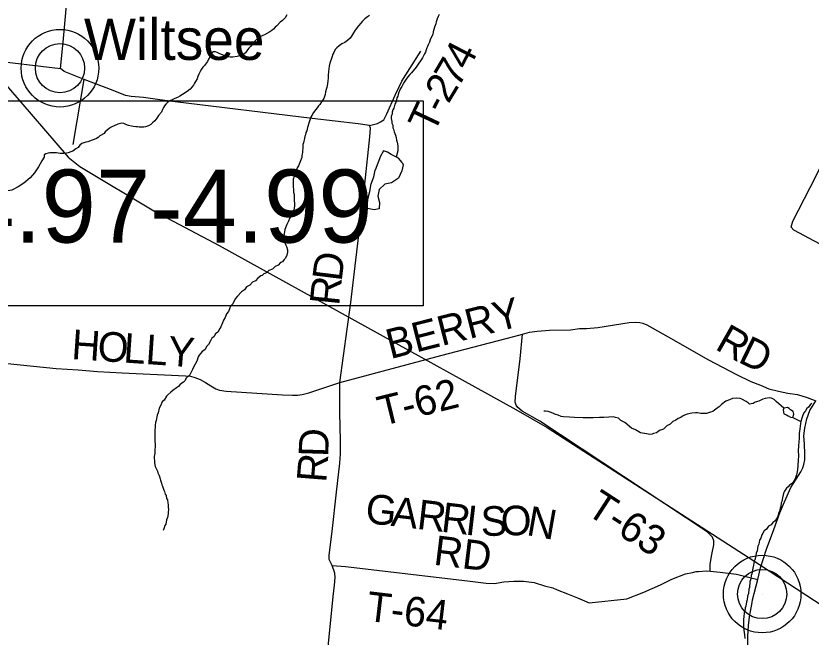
# Model space of a CAD drawing. Extents: x 0 to 39.3, y -3.9 to 22.
# Drawn here: x 6.099 to 7.624, y 15.488 to 16.679 of the extents above; entities that cross this region are included whole.
import ezdxf

# ---------------------------------------------------------------- set-up
doc = ezdxf.new("R2010")
doc.units = 0
for name, color, linetype in [('GM_X_County_Road', 7, 'Continuous'), ('GM_X_County_Road_Text', 7, 'Continuous'), ('GM_X_Minor_Lake', 7, 'Continuous'), ('GM_X_Minor_River', 7, 'Continuous'), ('GM_X_Rail_Line', 7, 'Continuous'), ('GM_X_State_Route', 7, 'Continuous'), ('GM_X_Township_Road', 7, 'Continuous'), ('GM_X_Township_Road_Text', 7, 'Continuous'), ('GM_X_Unincorporated', 7, 'Continuous'), ('GM_X_Unincorporated_Location', 7, 'Continuous'), ('GM_X_Unincorporated_Text', 7, 'Continuous'), ('SH_Text', 7, 'Continuous')]:
    doc.layers.add(name, color=color, linetype=linetype)

msp = doc.modelspace()

# ---------------------------------------------------------------- linework, layer by layer
at = {"layer": 'GM_X_County_Road'}
for points in [[(6.7775, 16.4687), (6.7555, 16.4724), (6.6671, 16.4823), (6.4045, 16.5144), (6.3754, 16.5183), (6.3437, 16.5225), (6.3203, 16.5247), (6.3095, 16.5263), (6.2855, 16.5361), (6.2304, 16.5573), (6.1919, 16.5725), (6.1845, 16.5782), (6.1899, 16.6288), (6.2, 16.7428), (6.219, 16.9267), (6.2251, 16.9948), (6.2341, 17.078), (6.2503, 17.2345), (6.2622, 17.3562), (6.267, 17.3776)], [(6.7203, 15.976), (6.7413, 16.1292), (6.7681, 16.3564), (6.7779, 16.4474), (6.7791, 16.4635), (6.7775, 16.4687)], [(6.0268, 16.0202), (6.0514, 16.0165), (6.0628, 16.015), (6.083, 16.0122), (6.1762, 16.0027), (6.2187, 16.0002), (6.2558, 15.9974), (6.3028, 15.9945), (6.4246, 15.9891), (6.4343, 15.9879), (6.4423, 15.9854), (6.4525, 15.9817), (6.4631, 15.976), (6.4731, 15.9697), (6.4828, 15.9637), (6.4896, 15.9614), (6.5024, 15.9597), (6.6105, 15.9526), (6.6296, 15.9515), (6.6393, 15.9517), (6.6484, 15.9529), (6.661, 15.956), (6.7203, 15.976)]]:
    msp.add_lwpolyline(points, dxfattribs=at)
at = {"layer": 'GM_X_Minor_Lake'}
for points in [[(6.8402, 16.398), (6.8328, 16.4061), (6.8188, 16.4136), (6.8117, 16.4179), (6.8041, 16.4203), (6.7986, 16.4101), (6.7883, 16.3835)], [(6.8402, 16.398), (6.842, 16.3932), (6.8395, 16.3818), (6.8332, 16.3682), (6.8198, 16.359), (6.8068, 16.3562), (6.796, 16.3461), (6.7935, 16.3336), (6.7967, 16.321), (6.7957, 16.3092), (6.7862, 16.3075), (6.7734, 16.3096), (6.7735, 16.3199), (6.7748, 16.3301), (6.7777, 16.3426), (6.7806, 16.357), (6.7854, 16.3702), (6.7883, 16.3835)], [(7.5895, 15.909), (7.5911, 15.915), (7.59, 15.9204), (7.5848, 15.9239), (7.5822, 15.9262), (7.5788, 15.9282), (7.5719, 15.9268), (7.5707, 15.9234), (7.5721, 15.9157)], [(7.5721, 15.9157), (7.5774, 15.9141), (7.5804, 15.9118), (7.5845, 15.9094), (7.5895, 15.909)], [(7.5895, 15.909), (7.6047, 15.901)]]:
    msp.add_lwpolyline(points, dxfattribs=at)
at = {"layer": 'GM_X_Minor_River'}
for points in [[(6.6189, 16.6809), (6.6158, 16.6757), (6.6103, 16.6704), (6.6061, 16.6671), (6.5999, 16.6603), (6.5964, 16.6574), (6.593, 16.654), (6.5899, 16.6514), (6.586, 16.6484), (6.5757, 16.6429), (6.5726, 16.6418), (6.5657, 16.6385), (6.5619, 16.6351), (6.5564, 16.6291), (6.5529, 16.625), (6.5494, 16.6205), (6.546, 16.6172), (6.5436, 16.6142), (6.5394, 16.6085), (6.5363, 16.6055), (6.5313, 16.6033), (6.5236, 16.6012), (6.5149, 16.5998), (6.5103, 16.5999), (6.5065, 16.6007), (6.502, 16.602), (6.4937, 16.6051), (6.4891, 16.6071), (6.485, 16.6087), (6.482, 16.6099), (6.4782, 16.6104), (6.4751, 16.6081), (6.4731, 16.6047), (6.4708, 16.5998), (6.4688, 16.5961), (6.4665, 16.5919), (6.4645, 16.5889), (6.4606, 16.584), (6.4579, 16.5807), (6.4552, 16.5769), (6.4524, 16.5724), (6.4501, 16.5675), (6.4481, 16.5626), (6.4465, 16.5584), (6.4438, 16.5535), (6.4418, 16.5501), (6.4398, 16.5464), (6.4336, 16.5389), (6.4278, 16.534), (6.4186, 16.5281), (6.4133, 16.5255), (6.409, 16.5229), (6.4041, 16.5207), (6.3987, 16.5182), (6.3945, 16.516), (6.3899, 16.513), (6.3868, 16.51), (6.3844, 16.5066), (6.3825, 16.5032), (6.3805, 16.4995), (6.3781, 16.4942), (6.3727, 16.4878), (6.3692, 16.4833), (6.3657, 16.4781), (6.3611, 16.474), (6.358, 16.471), (6.3534, 16.4684), (6.348, 16.4662), (6.3446, 16.4659), (6.3412, 16.4659), (6.3355, 16.4657), (6.3324, 16.4661), (6.3294, 16.4661), (6.3241, 16.467), (6.321, 16.4674), (6.315, 16.4691), (6.3101, 16.471), (6.3063, 16.4726), (6.3025, 16.4735)], [(6.7774, 16.68), (6.7732, 16.6771), (6.7686, 16.6734), (6.7631, 16.6681), (6.7608, 16.6651), (6.7562, 16.6599), (6.7499, 16.6516), (6.7464, 16.6467), (6.7445, 16.6433), (6.7425, 16.6403), (6.7402, 16.6366), (6.7352, 16.6317), (6.7298, 16.6284), (6.7244, 16.6254), (6.7194, 16.6217), (6.7148, 16.618), (6.7117, 16.6146), (6.7089, 16.609), (6.7073, 16.6056), (6.705, 16.5995), (6.7038, 16.5957), (6.7025, 16.592), (6.7013, 16.5882), (6.7001, 16.5829), (6.6993, 16.5779), (6.6988, 16.5722), (6.6983, 16.565), (6.6978, 16.5601), (6.6977, 16.554), (6.6969, 16.5495), (6.6961, 16.5453), (6.6956, 16.5415), (6.6944, 16.5381), (6.6932, 16.5332), (6.6924, 16.5282), (6.6912, 16.5248), (6.69, 16.521), (6.6853, 16.5143), (6.6818, 16.5094), (6.6798, 16.5064), (6.6771, 16.5026), (6.6744, 16.4996), (6.6701, 16.494), (6.667, 16.4884), (6.6646, 16.4846), (6.6614, 16.4755), (6.6586, 16.4649), (6.657, 16.4589), (6.6554, 16.4555), (6.6546, 16.4513), (6.6534, 16.4483), (6.6525, 16.4437), (6.6513, 16.4388), (6.6505, 16.4358), (6.6497, 16.4324), (6.6492, 16.4286), (6.6492, 16.4251), (6.6487, 16.4213), (6.6487, 16.4179), (6.6482, 16.4141), (6.6478, 16.4111), (6.6474, 16.4077)], [(6.9109, 16.6815), (6.9093, 16.6777), (6.9073, 16.6732), (6.9049, 16.6675), (6.9045, 16.6637), (6.9017, 16.6577), (6.9009, 16.6532), (6.8997, 16.6486), (6.8985, 16.6437), (6.8961, 16.6388), (6.8937, 16.6331), (6.8921, 16.6286), (6.8901, 16.6237), (6.8889, 16.6206), (6.8874, 16.6176), (6.8862, 16.6142), (6.8846, 16.6097), (6.883, 16.6063), (6.8791, 16.5988), (6.8752, 16.5927), (6.872, 16.5882), (6.8666, 16.5807), (6.8643, 16.5777), (6.8604, 16.5732), (6.8577, 16.5702), (6.855, 16.5665), (6.8511, 16.562), (6.8476, 16.5578), (6.8437, 16.5518), (6.8413, 16.5477), (6.8394, 16.5439), (6.837, 16.5398), (6.835, 16.5356), (6.8339, 16.5326), (6.8326, 16.5284), (6.8315, 16.5254), (6.8299, 16.522), (6.829, 16.5175), (6.8278, 16.5133), (6.8262, 16.5099), (6.8238, 16.5023), (6.8223, 16.4989), (6.821, 16.4944), (6.8206, 16.4914), (6.819, 16.4864), (6.8189, 16.4823), (6.82, 16.4769), (6.8203, 16.4731), (6.8218, 16.4693), (6.8224, 16.4647), (6.8235, 16.4616), (6.8246, 16.4571), (6.8261, 16.4536), (6.8271, 16.4505), (6.8286, 16.446), (6.8293, 16.441), (6.8303, 16.4368), (6.831, 16.4337), (6.8317, 16.4292), (6.832, 16.4246), (6.832, 16.4204), (6.8286, 16.4084)], [(6.3025, 16.4735), (6.2949, 16.4717), (6.2818, 16.4655), (6.278, 16.4629), (6.2745, 16.4599), (6.2703, 16.4565), (6.2687, 16.4535), (6.2603, 16.4491), (6.2568, 16.4457), (6.2537, 16.4443), (6.2491, 16.4424), (6.2457, 16.4406), (6.2373, 16.4373), (6.2335, 16.437), (6.2293, 16.4359), (6.2254, 16.4345), (6.222, 16.4311), (6.2188, 16.4266), (6.2142, 16.424), (6.2081, 16.4196), (6.2046, 16.4185), (6.1997, 16.4163), (6.1959, 16.416), (6.1909, 16.4153), (6.1871, 16.415), (6.1841, 16.4154), (6.1799, 16.4159), (6.1769, 16.4163), (6.1734, 16.4168), (6.1696, 16.4165), (6.1643, 16.4162), (6.1609, 16.4158), (6.1567, 16.4148), (6.1536, 16.4126), (6.1535, 16.4084)], [(6.1535, 16.4084), (6.149, 16.4012), (6.1423, 16.3895), (6.1349, 16.3783), (6.1268, 16.3685), (6.1141, 16.3585), (6.1037, 16.3515), (6.0914, 16.3448), (6.0789, 16.3428), (6.0679, 16.3437), (6.0474, 16.3441), (6.0352, 16.3413), (6.0221, 16.3274), (6.0135, 16.3143), (6.0042, 16.3015), (5.9944, 16.2868), (5.9847, 16.2726), (5.9745, 16.2572), (5.9633, 16.2441), (5.9525, 16.2306), (5.9439, 16.2178), (5.9327, 16.2051)], [(6.6474, 16.4077), (6.6411, 16.3918), (6.6387, 16.388), (6.6375, 16.3831), (6.6335, 16.3748), (6.6331, 16.3714), (6.6311, 16.3661), (6.6309, 16.3535), (6.6315, 16.344), (6.6318, 16.3413), (6.6328, 16.3368), (6.6328, 16.3326), (6.633, 16.3265), (6.6336, 16.3181), (6.6336, 16.315), (6.6331, 16.3105), (6.6315, 16.3033), (6.6291, 16.2999), (6.6271, 16.2938), (6.624, 16.2905), (6.622, 16.2856), (6.6185, 16.2791), (6.6161, 16.2727), (6.6149, 16.2693), (6.6136, 16.261), (6.6127, 16.2549), (6.613, 16.2507), (6.6152, 16.2442), (6.617, 16.2396), (6.6181, 16.2369), (6.6199, 16.2308), (6.6202, 16.2258), (6.6189, 16.2205), (6.6165, 16.2145), (6.6135, 16.2122), (6.6107, 16.2077), (6.6065, 16.2059), (6.6022, 16.201), (6.5965, 16.1988), (6.5914, 16.1932), (6.5845, 16.1907), (6.5799, 16.1862), (6.5749, 16.1844), (6.5714, 16.1814), (6.5687, 16.1803), (6.5633, 16.1762), (6.559, 16.1713), (6.5529, 16.1684), (6.5478, 16.1624), (6.5417, 16.1594), (6.5374, 16.1538), (6.5316, 16.1501), (6.5239, 16.1415), (6.52, 16.1366), (6.5152, 16.1271), (6.5106, 16.1223), (6.507, 16.1124), (6.5031, 16.1079), (6.5003, 16.1004), (6.4975, 16.0959), (6.4955, 16.0906), (6.492, 16.0826), (6.4904, 16.0796), (6.4865, 16.0728), (6.4818, 16.0695), (6.4787, 16.0638), (6.4752, 16.0612), (6.4725, 16.0559), (6.4685, 16.0488), (6.4654, 16.0458), (6.4615, 16.0386), (6.4565, 16.0357), (6.4541, 16.0323), (6.4506, 16.0285), (6.4487, 16.0251), (6.4462, 16.0168), (6.4404, 16.0066), (6.4376, 16.001), (6.4364, 15.9983), (6.4328, 15.9908), (6.4251, 15.9837), (6.4239, 15.9799), (6.4204, 15.9769), (6.4177, 15.9747), (6.4138, 15.9717), (6.4107, 15.9683), (6.4069, 15.9661), (6.3999, 15.9605), (6.3961, 15.9572), (6.3903, 15.9527), (6.3883, 15.9497), (6.3832, 15.9421), (6.3794, 15.9388), (6.3766, 15.9316), (6.3742, 15.9271), (6.3721, 15.9176), (6.3701, 15.9131), (6.3684, 15.9032), (6.3668, 15.8994), (6.366, 15.8945), (6.3657, 15.8808)], [(7.5719, 15.9268), (7.5571, 15.9398), (7.5534, 15.9437), (7.5485, 15.9457), (7.5447, 15.9465), (7.5359, 15.9455), (7.5317, 15.9441), (7.524, 15.9404), (7.5171, 15.9386), (7.5129, 15.936), (7.5091, 15.935), (7.5064, 15.9346), (7.5034, 15.937), (7.4997, 15.9397), (7.4917, 15.944), (7.488, 15.9452), (7.4807, 15.9457), (7.4735, 15.9455), (7.4677, 15.9425), (7.4605, 15.94), (7.4527, 15.9336), (7.4477, 15.9292), (7.4442, 15.9269), (7.4388, 15.9232), (7.4357, 15.9206), (7.4311, 15.9192), (7.4235, 15.9166), (7.417, 15.9164), (7.4128, 15.9168), (7.4064, 15.9177), (7.4029, 15.9177), (7.3957, 15.9171), (7.3865, 15.9154), (7.3816, 15.9135), (7.3777, 15.9117), (7.3742, 15.9091), (7.3693, 15.9073), (7.365, 15.9035), (7.3593, 15.9014), (7.3542, 15.8961), (7.3473, 15.8932), (7.3415, 15.8868), (7.3334, 15.8839), (7.3276, 15.8794), (7.3223, 15.878), (7.3192, 15.8769), (7.3147, 15.8766), (7.3086, 15.8775), (7.2972, 15.8792), (7.2874, 15.8851), (7.2799, 15.8886), (7.2671, 15.8991), (7.2596, 15.9031), (7.2547, 15.9077), (7.2494, 15.909), (7.2445, 15.9102), (7.2365, 15.9096), (7.2269, 15.909), (7.2182, 15.9087), (7.2064, 15.9082), (7.1869, 15.9081), (7.1702, 15.9088), (7.1611, 15.9093), (7.1493, 15.9103), (7.1447, 15.9111), (7.1391, 15.9131), (7.1326, 15.9155), (7.1289, 15.9175), (7.1239, 15.9191), (7.1202, 15.9203), (7.1148, 15.9208), (7.1114, 15.9212)], [(7.6193, 15.9286), (7.6162, 15.926), (7.6138, 15.9214), (7.6103, 15.9181), (7.6087, 15.9135), (7.6063, 15.9075), (7.6047, 15.901), (7.6039, 15.8973), (7.6025, 15.887), (7.6021, 15.8821), (7.6016, 15.8786), (7.6015, 15.8707), (7.6009, 15.8604), (7.6001, 15.8562), (7.5998, 15.8429), (7.6001, 15.8379), (7.6, 15.8326), (7.5996, 15.8288), (7.5995, 15.825), (7.599, 15.8197), (7.5986, 15.817), (7.5985, 15.8083), (7.5972, 15.8018), (7.5964, 15.7992), (7.5952, 15.795), (7.5932, 15.7901), (7.5885, 15.7833), (7.5831, 15.7792), (7.5804, 15.7762), (7.5773, 15.7732), (7.573, 15.7676), (7.5718, 15.765), (7.5709, 15.7608), (7.5693, 15.7551), (7.568, 15.7479), (7.5669, 15.7453), (7.566, 15.738), (7.5652, 15.735), (7.5639, 15.7286), (7.5619, 15.7255), (7.5611, 15.7214), (7.5591, 15.7165), (7.5548, 15.7101), (7.5509, 15.7075), (7.5474, 15.703), (7.5428, 15.7007), (7.5389, 15.6947), (7.5343, 15.6918), (7.5319, 15.6869), (7.5296, 15.6842), (7.5279, 15.6774), (7.5256, 15.6736), (7.5239, 15.6661), (7.5223, 15.6623), (7.5207, 15.6535), (7.5187, 15.6486), (7.5174, 15.6407), (7.5162, 15.6361), (7.5154, 15.6335), (7.5141, 15.6255), (7.5128, 15.6198), (7.5107, 15.6088), (7.5095, 15.6062), (7.509, 15.5993), (7.507, 15.5936), (7.5061, 15.583), (7.5052, 15.58), (7.5043, 15.5712), (7.5023, 15.5663), (7.5014, 15.5591), (7.5006, 15.5557), (7.4993, 15.547), (7.4977, 15.5436), (7.4969, 15.5371), (7.496, 15.5341), (7.4955, 15.5265), (7.4947, 15.5219), (7.4944, 15.5063), (7.4951, 15.5017), (7.4957, 15.496), (7.4968, 15.4926), (7.4974, 15.4853)], [(7.6259, 15.9357), (7.6224, 15.9331), (7.6193, 15.9286)], [(6.3657, 15.8808), (6.3656, 15.8739), (6.3655, 15.8652), (6.3661, 15.8557), (6.3658, 15.8442), (6.3654, 15.8404), (6.3645, 15.834), (6.3645, 15.8309), (6.3647, 15.8256), (6.3651, 15.8218), (6.3665, 15.8149), (6.3676, 15.8122), (6.3705, 15.8057), (6.3716, 15.803), (6.3738, 15.7977), (6.3756, 15.7915), (6.3766, 15.7885), (6.3781, 15.7827), (6.3788, 15.7797), (6.3806, 15.777), (6.3828, 15.7697), (6.3842, 15.767), (6.3857, 15.7621), (6.3875, 15.7594), (6.3882, 15.7536), (6.3897, 15.751), (6.3903, 15.7449), (6.391, 15.7418), (6.3913, 15.7361), (6.3916, 15.733), (6.3915, 15.7269), (6.3911, 15.7243), (6.3898, 15.7171), (6.3882, 15.7125), (6.3865, 15.7046), (6.385, 15.7016), (6.3834, 15.6974), (6.3815, 15.6923)]]:
    msp.add_lwpolyline(points, dxfattribs=at)
at = {"layer": 'GM_X_Rail_Line'}
msp.add_lwpolyline([(5.9697, 16.6744), (6.1991, 16.4081), (6.2218, 16.3901), (6.3667, 16.3031), (6.4893, 16.2389), (7.0583, 15.9241), (7.1182, 15.89), (7.5253, 15.6271), (8.2122, 15.1777), (8.5334, 14.9668), (8.7, 14.8573)], dxfattribs=at)
at = {"layer": 'GM_X_State_Route'}
for points in [[(7.5122, 15.5592), (7.522, 15.5982), (7.5272, 15.6204), (7.5387, 15.6566), (7.5526, 15.6942), (7.5643, 15.7262), (7.5732, 15.747), (7.5854, 15.7747), (7.6044, 15.8045), (7.6082, 15.8123), (7.6103, 15.8185), (7.6123, 15.8277), (7.6125, 15.839), (7.6114, 15.8576), (7.6105, 15.8736), (7.6124, 15.8884), (7.6161, 15.9066), (7.622, 15.9225), (7.6335, 15.9408)], [(7.5062, 14.9738), (7.5079, 14.9918), (7.5101, 15.0116), (7.5109, 15.0289), (7.5099, 15.057), (7.5076, 15.0895), (7.5041, 15.1204), (7.4986, 15.1789), (7.4952, 15.2192), (7.4944, 15.2368), (7.4931, 15.2662), (7.4943, 15.2903), (7.4956, 15.3156), (7.4974, 15.3466), (7.5005, 15.3886), (7.5027, 15.4261), (7.503, 15.4463), (7.5032, 15.4895), (7.5041, 15.5091), (7.506, 15.5264), (7.511, 15.5543), (7.5122, 15.5592)]]:
    msp.add_lwpolyline(points, dxfattribs=at)
at = {"layer": 'GM_X_Township_Road'}
for p, q in [((6.855, 16.5784), (6.876, 16.6113)), ((6.2088, 16.4325), (6.2304, 16.5573))]:
    msp.add_line(p, q, dxfattribs=at)
for points in [[(5.7323, 16.6297), (5.7442, 16.6283), (5.8452, 16.6172), (6.0439, 16.5946), (6.1845, 16.5782)], [(6.7775, 16.4687), (6.7853, 16.4706), (6.7925, 16.4728), (6.7982, 16.4758), (6.8047, 16.4797), (6.8107, 16.4913), (6.8264, 16.5269), (6.8338, 16.5416), (6.8394, 16.5541), (6.855, 16.5784)], [(7.7438, 16.1805), (7.7386, 16.1846), (7.7284, 16.1927), (7.7122, 16.2024), (7.6705, 16.2262), (7.5912, 16.2683), (7.5862, 16.2741), (7.5891, 16.2854), (7.6332, 16.3712), (7.652, 16.409)], [(6.7203, 15.976), (6.9139, 16.0279), (7.0542, 16.0644), (7.071, 16.0689), (7.0844, 16.0723), (7.0989, 16.0746), (7.1223, 16.0766), (7.1631, 16.077), (7.1802, 16.0793), (7.1934, 16.0793), (7.2151, 16.0817), (7.2751, 16.0912), (7.2871, 16.0917), (7.2959, 16.0914), (7.3016, 16.09), (7.3093, 16.0869), (7.3504, 16.0635), (7.4277, 16.0193), (7.4813, 15.9914), (7.5089, 15.9778), (7.5275, 15.971), (7.5435, 15.964), (7.5621, 15.9592), (7.5796, 15.9557), (7.598, 15.9528), (7.6166, 15.9474), (7.6335, 15.9408)], [(7.4308, 15.6139), (7.4305, 15.6276), (7.434, 15.6461), (7.4376, 15.6644), (7.4376, 15.6724), (7.4354, 15.6795), (7.4251, 15.6896), (7.1041, 15.9021), (7.0701, 15.9212), (7.0621, 15.9278), (7.0584, 15.9323), (7.057, 15.9386), (7.0573, 15.9495), (7.0664, 16.0213), (7.071, 16.0689)], [(6.5996, 14.4912), (6.7035, 15.5268), (6.7077, 15.5659), (6.7103, 15.5876), (6.7116, 15.6022), (6.7108, 15.6105), (6.7059, 15.6251), (6.7001, 15.6366), (6.6999, 15.6452), (6.7056, 15.6903), (6.714, 15.7659), (6.7205, 15.8216), (6.7215, 15.8394), (6.722, 15.8649), (6.7205, 15.9178), (6.7205, 15.9507), (6.7203, 15.976)], [(6.7059, 15.6251), (6.7312, 15.6233), (6.9655, 15.5959), (7.0008, 15.5912), (7.0172, 15.5908), (7.0351, 15.5937), (7.054, 15.5952), (7.0726, 15.5952), (7.0929, 15.5923), (7.1127, 15.5864), (7.1287, 15.5821), (7.1371, 15.5787)], [(7.1371, 15.5787), (7.1568, 15.5707), (7.1765, 15.5631), (7.1984, 15.5536), (7.2706, 15.5614), (7.3036, 15.5739), (7.3354, 15.5878), (7.3569, 15.599), (7.3837, 15.609), (7.3966, 15.6118), (7.4036, 15.6134), (7.4081, 15.6137)], [(7.4081, 15.6137), (7.423, 15.6148), (7.4308, 15.6139), (7.4501, 15.6123), (7.481, 15.6086), (7.522, 15.5982)]]:
    msp.add_lwpolyline(points, dxfattribs=at)
at = {"layer": 'GM_X_Unincorporated'}
for centre, radius in [((6.1837, 16.5788), 0.0744), ((6.1837, 16.5788), 0.0472), ((7.5305, 15.5704), 0.0744), ((7.5305, 15.5704), 0.0472)]:
    msp.add_circle(centre, radius, dxfattribs=at)
at = {"layer": 'GM_X_Unincorporated_Location'}
for p, q in [((6.1837, 16.5788), (6.1837, 16.5788)), ((7.5305, 15.5704), (7.5305, 15.5704))]:
    msp.add_line(p, q, dxfattribs=at)
at = {"layer": 'SH_Text'}
msp.add_lwpolyline([(5.4598, 16.5161), (6.8805, 16.5161), (6.8805, 16.1228), (5.4598, 16.1228)], close=True, dxfattribs=at)

# ---------------------------------------------------------------- texts
at = {"layer": 'GM_X_County_Road_Text'}
for s, rotation, p in [('D', 82.9479, (6.7238, 16.1685)), ('R', 84.0294, (6.719, 16.1223)), ('H', 356.1303, (6.2046, 16.0212)), ('O', 356.1323, (6.2545, 16.0178)), ('L', 356.1315, (6.3043, 16.0145)), ('L', 356.1251, (6.3467, 16.0116)), ('Y', 355.4508, (6.389, 16.0087))]:
    msp.add_text(s, height=0.0568, rotation=rotation, dxfattribs=at).set_placement(p)
at = {"layer": 'GM_X_Township_Road_Text'}
for s, height, rotation, p in [('4', 0.0568, 62.5097, (6.9666, 16.5727)), ('7', 0.0568, 59.3672, (6.9471, 16.5396)), ('2', 0.0568, 58.9305, (6.9288, 16.5092)), ('-', 0.0568, 62.7664, (6.9187, 16.4893)), ('T', 0.0568, 64.769, (6.9008, 16.4514)), ('BERRY', 0.05682, 14.2852, (6.8174, 16.0208)), ('R', 0.0568, 330.4507, (7.438, 16.041)), ('D', 0.0568, 334.1489, (7.482, 16.0162)), ('T-62', 0.05682, 13.8652, (6.8009, 15.8923)), ('D', 0.0568, 88.2337, (6.6981, 15.8327)), ('R', 0.0568, 85.3934, (6.6942, 15.7831)), ('T-63', 0.05682, 327.0953, (7.1903, 15.7253)), ('G', 0.0568, 353.3259, (6.7675, 15.7071)), ('A', 0.0568, 353.3245, (6.8171, 15.7013)), ('R', 0.0568, 353.3266, (6.8668, 15.6955)), ('R', 0.0568, 353.3247, (6.9131, 15.6901)), ('I', 0.0568, 353.3263, (6.9595, 15.6846)), ('S', 0.0568, 1.3225, (6.9913, 15.6815)), ('O', 0.0568, 1.2696, (7.0296, 15.6824)), ('N', 0.0568, 349.9454, (7.0766, 15.6838)), ('RD', 0.05682, 353.0591, (6.8987, 15.6267)), ('T-64', 0.05682, 353.2698, (6.7698, 15.5193))]:
    msp.add_text(s, height=height, rotation=rotation, dxfattribs=at).set_placement(p)
at = {"layer": 'GM_X_Unincorporated_Text'}
msp.add_text('Wiltsee', height=0.07898, rotation=0, dxfattribs=at).set_placement((6.2297, 16.5947))
at = {"layer": 'SH_Text'}
msp.add_text('SLM: 4.97-4.99', height=0.14, dxfattribs=at).set_placement((5.5033, 16.2444))

doc.saveas('drawing.dxf')
